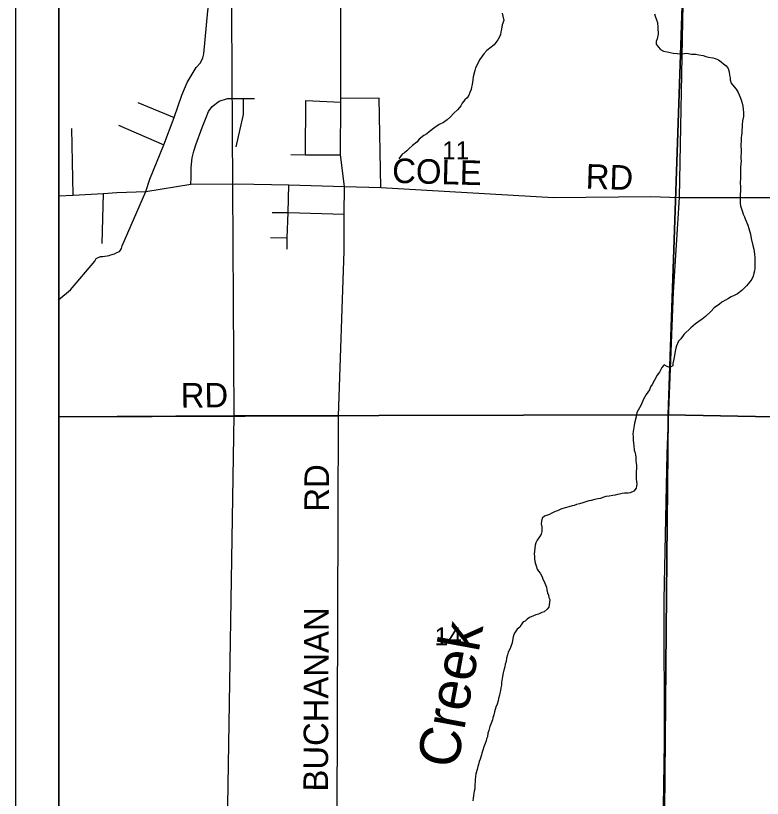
# Model space of a CAD drawing. Extents: x 0 to 34, y 0 to 22.
# Drawn here: x 23.417 to 25.144, y 17.024 to 18.836 of the extents above; entities that cross this region are included whole.
import ezdxf

# ---------------------------------------------------------------- set-up
doc = ezdxf.new("R2010")
doc.units = 0
for name, color, linetype in [('GM_X_County_Road', 7, 'Continuous'), ('GM_X_Minor_River', 7, 'Continuous'), ('GM_X_Minor_River_Text', 7, 'Continuous'), ('GM_X_Section', 7, 'Continuous'), ('GM_X_Section_Text', 7, 'Continuous'), ('GM_X_Township_Road', 7, 'Continuous'), ('GM_X_Township_Road_Text', 7, 'Continuous'), ('SH_Data', 7, 'Continuous')]:
    doc.layers.add(name, color=color, linetype=linetype)

msp = doc.modelspace()

# ---------------------------------------------------------------- linework, layer by layer
at = {"layer": 'GM_X_County_Road'}
for points in [[(24.9527, 18.4155), (24.9614, 18.8646), (24.963, 18.9602), (24.9739, 19.182), (24.9749, 19.1969)], [(23.7182, 18.4291), (23.7274, 18.4574), (23.7597, 18.5372), (23.7834, 18.6002), (23.8012, 18.6519), (23.8134, 18.6813), (23.8345, 18.7159), (23.8441, 18.7268), (23.8496, 18.7388), (23.8517, 18.7479), (23.8613, 18.8473), (23.8762, 18.9492), (23.9004, 19.0127), (23.9305, 19.0946), (23.9629, 19.1735)], [(23.5167, 18.1789), (23.5437, 18.2013), (23.5999, 18.2677), (23.6026, 18.2741), (23.6126, 18.2785), (23.6186, 18.2788), (23.6327, 18.2812), (23.6369, 18.2823), (23.6453, 18.2848), (23.6511, 18.2877), (23.6568, 18.2899), (23.6595, 18.2929), (23.6615, 18.2974), (23.6627, 18.3031), (23.7182, 18.4291)], [(24.9139, 16.9052), (24.9179, 17.1535), (24.9168, 17.4836), (24.9237, 17.8223), (24.9385, 18.1961), (24.9527, 18.4155)]]:
    msp.add_lwpolyline(points, dxfattribs=at)
at = {"layer": 'GM_X_Minor_River'}
for points in [[(24.5424, 18.8417), (24.5442, 18.8348), (24.546, 18.825), (24.5425, 18.8147), (24.5405, 18.8049), (24.5396, 18.7984)], [(24.8944, 18.8406), (24.8966, 18.8353), (24.8996, 18.8269), (24.9018, 18.82), (24.9024, 18.8079), (24.903, 18.7931), (24.9006, 18.7828), (24.8986, 18.776), (24.8985, 18.7699)], [(24.5396, 18.7984), (24.5384, 18.7928), (24.5365, 18.7871), (24.5326, 18.7803), (24.528, 18.7743), (24.5238, 18.7686), (24.5172, 18.7634), (24.5069, 18.7559), (24.4996, 18.748), (24.4961, 18.7424), (24.49, 18.7341), (24.4861, 18.7254), (24.4807, 18.7152), (24.4791, 18.7095), (24.4751, 18.6948), (24.4743, 18.6879), (24.4735, 18.6822), (24.473, 18.6769), (24.4714, 18.6705), (24.4702, 18.6652), (24.4675, 18.658), (24.4651, 18.6524), (24.4617, 18.6459), (24.4563, 18.6411), (24.4501, 18.6335), (24.4467, 18.6271), (24.4401, 18.6192), (24.4298, 18.6095), (24.4228, 18.6016), (24.4152, 18.5952), (24.4064, 18.5892), (24.3968, 18.584), (24.3865, 18.5773), (24.3731, 18.5672), (24.3678, 18.5623), (24.3609, 18.5586), (24.3506, 18.5499), (24.3452, 18.5436), (24.3348, 18.5357), (24.3264, 18.5282), (24.3218, 18.5229), (24.3164, 18.5188), (24.3111, 18.5155), (24.3069, 18.5098), (24.303, 18.5045)], [(24.8985, 18.7699), (24.903, 18.7642), (24.9086, 18.7581), (24.9158, 18.7538), (24.9238, 18.7522), (24.9313, 18.7506), (24.9378, 18.7494), (24.9469, 18.7486), (24.9537, 18.7481), (24.9635, 18.7488), (24.9696, 18.7495), (24.9802, 18.7471), (24.9901, 18.747), (24.9976, 18.7454), (25.0071, 18.7441), (25.0135, 18.7418), (25.0196, 18.7398), (25.0294, 18.7386), (25.0351, 18.737), (25.0427, 18.7342), (25.0491, 18.7296), (25.0543, 18.725), (25.0603, 18.72), (25.0652, 18.7135), (25.0674, 18.7059), (25.068, 18.6987), (25.0699, 18.6926), (25.0702, 18.6873), (25.0724, 18.68), (25.0791, 18.6712), (25.084, 18.6659), (25.0881, 18.6586), (25.091, 18.6529), (25.0955, 18.6414), (25.0977, 18.6335), (25.0991, 18.627), (25.1002, 18.6198), (25.1008, 18.6122), (25.1003, 18.6027), (25.0987, 18.5924), (25.0978, 18.5837), (25.0965, 18.5655), (25.096, 18.5591), (25.0952, 18.5538), (25.0952, 18.5481), (25.0946, 18.5352), (25.0949, 18.5238), (25.0947, 18.5056), (25.095, 18.4999), (25.0941, 18.4851), (25.0939, 18.4699), (25.0934, 18.4574), (25.0933, 18.4513), (25.0935, 18.4373), (25.0934, 18.4297), (25.093, 18.4232), (25.0928, 18.408), (25.0931, 18.4016), (25.0938, 18.3959), (25.0982, 18.3822), (25.1, 18.3768), (25.103, 18.3707), (25.1048, 18.3654), (25.1104, 18.3509), (25.1129, 18.3437), (25.1166, 18.3304), (25.1187, 18.3201), (25.1223, 18.3041), (25.1245, 18.2957), (25.1263, 18.2836), (25.1266, 18.276), (25.1268, 18.2665), (25.1271, 18.26), (25.1267, 18.2513), (25.1262, 18.2456), (25.1246, 18.2399), (25.1227, 18.2328), (25.1199, 18.2259), (25.1157, 18.2199), (25.108, 18.2109), (25.1022, 18.2053), (25.0965, 18.2), (25.0869, 18.1921), (25.0793, 18.1884), (25.0724, 18.1855), (25.0656, 18.1814), (25.0591, 18.1773), (25.0503, 18.1732), (25.0453, 18.1679), (25.0327, 18.1597), (25.025, 18.1514), (25.0131, 18.1398), (25.0047, 18.1331), (24.9951, 18.1267), (24.9894, 18.123), (24.9787, 18.1136), (24.963, 18.0982), (24.9556, 18.088), (24.9506, 18.0828), (24.946, 18.0718), (24.944, 18.0665)], [(24.944, 18.0665), (24.9428, 18.0597), (24.94, 18.0446), (24.9387, 18.0381), (24.9375, 18.0305), (24.9371, 18.0252), (24.9295, 18.0215), (24.9227, 18.0246), (24.917, 18.0277), (24.912, 18.0217), (24.9066, 18.0104), (24.9012, 18.0036), (24.8946, 17.9923), (24.8892, 17.9825), (24.8853, 17.9764), (24.8833, 17.97), (24.8756, 17.9587), (24.8725, 17.9534), (24.8691, 17.9481), (24.8636, 17.9353), (24.8601, 17.9281), (24.8566, 17.9229), (24.8535, 17.9176), (24.8527, 17.907)], [(24.8527, 17.907), (24.8487, 17.8926), (24.8475, 17.8869), (24.8459, 17.8782), (24.8451, 17.8733), (24.845, 17.8672), (24.8453, 17.8622), (24.8452, 17.8543), (24.8463, 17.8452), (24.8466, 17.8406), (24.848, 17.83), (24.8498, 17.8239), (24.8505, 17.8193), (24.8512, 17.814), (24.8519, 17.8056), (24.8522, 17.8007), (24.8533, 17.7935), (24.8532, 17.7874), (24.8527, 17.7806), (24.8525, 17.7635), (24.8532, 17.7578), (24.8535, 17.7521), (24.8531, 17.7464), (24.8527, 17.7419), (24.8469, 17.7355), (24.8385, 17.7314), (24.834, 17.7307), (24.8252, 17.7304), (24.8199, 17.7301), (24.8134, 17.7286), (24.8089, 17.7271), (24.8039, 17.7257), (24.7986, 17.725), (24.7902, 17.7235), (24.7819, 17.7225), (24.775, 17.7207), (24.7701, 17.7181), (24.7636, 17.7174), (24.7568, 17.7159), (24.7484, 17.7137), (24.7431, 17.7127), (24.7385, 17.7112), (24.7332, 17.7094), (24.7286, 17.7083), (24.7214, 17.7057), (24.7142, 17.7042), (24.7092, 17.702), (24.7043, 17.7009), (24.6966, 17.6987), (24.6909, 17.6973), (24.6826, 17.6951), (24.678, 17.6936), (24.67, 17.6899), (24.665, 17.6884), (24.6574, 17.6844), (24.6517, 17.6814), (24.6452, 17.6792), (24.6406, 17.6773), (24.6349, 17.6728), (24.6333, 17.6656), (24.6329, 17.6596), (24.6339, 17.6523), (24.6338, 17.6421), (24.6326, 17.636), (24.6287, 17.6293), (24.6233, 17.6217), (24.6202, 17.6157), (24.619, 17.61), (24.6182, 17.6036), (24.6173, 17.5964), (24.6165, 17.5895), (24.6168, 17.585), (24.6171, 17.5793), (24.6182, 17.5721), (24.6193, 17.5667), (24.6207, 17.5622), (24.6233, 17.5549), (24.6263, 17.5503), (24.63, 17.545), (24.6345, 17.537), (24.6367, 17.5312), (24.6393, 17.5263), (24.6426, 17.5187), (24.6445, 17.5133), (24.6459, 17.5065), (24.6473, 17.5), (24.6496, 17.4947), (24.6506, 17.4893), (24.6525, 17.484), (24.652, 17.4772), (24.6512, 17.4723), (24.65, 17.4666), (24.6461, 17.4617), (24.6393, 17.4557), (24.6339, 17.4542), (24.6263, 17.4505), (24.6202, 17.4487), (24.6145, 17.4468), (24.6053, 17.4424), (24.6, 17.439), (24.5958, 17.4345)], [(24.5958, 17.4345), (24.5912, 17.4323), (24.5866, 17.4255), (24.5831, 17.4206), (24.5773, 17.4154), (24.5723, 17.4086), (24.5696, 17.4033), (24.5677, 17.3976), (24.5664, 17.3893), (24.5652, 17.3844), (24.5613, 17.373), (24.5594, 17.3677), (24.5562, 17.3621), (24.5543, 17.3564), (24.5527, 17.3484), (24.5515, 17.3409), (24.5495, 17.3344), (24.5483, 17.3288), (24.5463, 17.3204), (24.5447, 17.3144), (24.5431, 17.306), (24.5423, 17.3015), (24.541, 17.2924), (24.5406, 17.2859), (24.5394, 17.2799), (24.5382, 17.2734), (24.5366, 17.2678), (24.5358, 17.2632), (24.5342, 17.2553), (24.533, 17.25), (24.531, 17.2424), (24.5279, 17.2352), (24.5259, 17.2299), (24.5247, 17.2243), (24.5231, 17.2171), (24.5208, 17.2106), (24.5196, 17.2057), (24.516, 17.1955), (24.5137, 17.1906), (24.5113, 17.1807), (24.5094, 17.1751), (24.5081, 17.1667), (24.5062, 17.1618), (24.5054, 17.1573), (24.503, 17.1509), (24.4995, 17.1429), (24.4979, 17.1353), (24.4952, 17.1289), (24.4944, 17.1244), (24.4912, 17.1145), (24.4893, 17.1092), (24.4873, 17.1024), (24.4861, 17.0975), (24.4841, 17.0907), (24.4817, 17.0805), (24.4805, 17.0748), (24.4797, 17.0668), (24.4796, 17.0615), (24.4792, 17.057), (24.4787, 17.0513), (24.4787, 17.046), (24.4775, 17.0407), (24.477, 17.0361), (24.4762, 17.0301), (24.475, 17.0244), (24.4742, 17.0179)]]:
    msp.add_lwpolyline(points, dxfattribs=at)
at = {"layer": 'GM_X_Section'}
msp.add_lwpolyline([(23.5167, 18.899), (23.5167, 17.9073), (23.9224, 17.9096), (23.916, 18.9723)], dxfattribs=at)
for points in [[(24.9624, 18.9716), (24.9267, 17.9117), (23.9224, 17.9096), (23.916, 18.9723)], [(26.0607, 18.8928), (26.0171, 17.9156), (26.0158, 17.891), (24.9267, 17.9117), (24.9624, 18.9716)], [(23.5167, 17.9073), (23.5167, 16.9109), (23.906, 16.9126), (23.9224, 17.9096)], [(24.9267, 17.9117), (24.9171, 16.9109), (23.906, 16.9126), (23.9224, 17.9096)], [(26.0158, 17.891), (25.9875, 16.9239), (25.9861, 16.8906), (24.9171, 16.9109), (24.9267, 17.9117)]]:
    msp.add_lwpolyline(points, close=True, dxfattribs=at)
at = {"layer": 'GM_X_Township_Road'}
for p, q in [((23.6992, 18.635), (23.7834, 18.6002)), ((24.0871, 18.5143), (24.088, 18.6401)), ((24.088, 18.6401), (24.1687, 18.6361)), ((23.6545, 18.5825), (23.7597, 18.5372)), ((23.5499, 18.4209), (23.5467, 18.575)), ((23.6188, 18.4247), (23.6157, 18.3084)), ((24.0066, 18.3225), (24.0445, 18.3215)), ((23.5167, 17.9077), (24.1639, 17.9096)), ((24.1604, 16.9066), (24.1639, 17.9096))]:
    msp.add_line(p, q, dxfattribs=at)
for points in [[(24.1778, 18.4409), (24.1684, 18.5138), (24.1687, 18.6361), (24.1687, 18.6441), (24.1694, 18.9087), (24.1701, 19.1767)], [(23.8218, 18.4463), (23.8227, 18.4612), (23.8227, 18.485), (23.8247, 18.5073), (23.8287, 18.5222), (23.8337, 18.5368), (23.8485, 18.5769), (23.8577, 18.6007), (23.8632, 18.6143), (23.8713, 18.626), (23.8877, 18.6381), (23.9065, 18.6446), (23.9214, 18.6446), (23.944, 18.6442), (23.9694, 18.6441)], [(23.9267, 18.5328), (23.9439, 18.6071), (23.944, 18.6442)], [(24.2617, 18.4385), (24.2574, 18.6453), (24.1687, 18.6441)], [(24.0537, 18.5145), (24.0871, 18.5143), (24.1684, 18.5138)], [(23.5167, 18.4191), (23.5499, 18.4209), (23.6188, 18.4247), (23.6506, 18.4264), (23.7182, 18.4291), (23.8218, 18.4463), (23.9278, 18.447), (24.0489, 18.4446), (24.1778, 18.4409)], [(24.0445, 18.2953), (24.0445, 18.3215), (24.0472, 18.3808), (24.0489, 18.4446)], [(24.1771, 18.2928), (24.1771, 18.3768), (24.1778, 18.4409)], [(24.1778, 18.4409), (24.2617, 18.4385), (24.6611, 18.4152), (24.8859, 18.4177), (24.9527, 18.4155)], [(24.9527, 18.4155), (24.9558, 18.4155), (25.567, 18.4152)], [(24.01, 18.3808), (24.0472, 18.3808), (24.1771, 18.3768)], [(24.1639, 17.9096), (24.1771, 18.2908), (24.1771, 18.2928)]]:
    msp.add_lwpolyline(points, dxfattribs=at)
at = {"layer": 'SH_Data'}
for points in [[(23.4167, 21), (30.4167, 21), (30.4167, 14), (23.4167, 14)], [(23.5167, 20.9), (30.3167, 20.9), (30.3167, 14.1), (23.5167, 14.1)]]:
    msp.add_lwpolyline(points, close=True, dxfattribs=at)

# ---------------------------------------------------------------- texts
at = {"layer": 'GM_X_Minor_River_Text'}
msp.add_text('Creek', height=0.09474, rotation=79.537, dxfattribs=at).set_placement((24.4377, 17.0903))
at = {"layer": 'GM_X_Section_Text'}
for s, p in [('11', (24.4036, 18.5033)), ('14', (24.3861, 17.3782))]:
    msp.add_text(s, height=0.04186, rotation=0, dxfattribs=at).set_placement(p)
at = {"layer": 'GM_X_Township_Road_Text'}
for s, rotation, p in [('COLE', 358.4233, (24.2872, 18.4493)), ('RD', 358.0252, (24.7348, 18.436)), ('RD', 0.4936, (23.7988, 17.9285)), ('RD', 90, (24.1417, 17.6878)), ('BUCHANAN', 89.7573, (24.1392, 17.0396))]:
    msp.add_text(s, height=0.05682, rotation=rotation, dxfattribs=at).set_placement(p)

doc.saveas('drawing.dxf')
